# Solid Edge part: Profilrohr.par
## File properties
Username: ahadarics
Dokumentum tartalom típus: 0
Author: ahadarics
Last saved by: ahadarics
Revision: 85
Sűrűség: 0,000 kg/m^3
Pontosság: 0,990
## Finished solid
Body 1: solid body, 6 faces, 6 edges, 0 vertices.
  Faces by surface: cone 2, cylinder 2, plane 2
  Edges by curve: circle 6
Bounding box of the edges (mm): 13.270 x 13.270 x 347.000, from (-6.635, -6.635, -328.5) to (6.635, 6.635, 18.5).
Cylindrical faces by radius (mm): R6 x1, R6.635 x1
Conical faces (half-angle, radius in mm at the cone's reference point): 15 deg R6.067 x2
Planar faces by outward normal: +z 1, -z 1
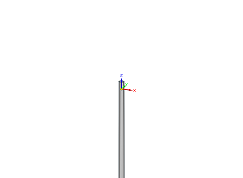
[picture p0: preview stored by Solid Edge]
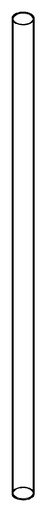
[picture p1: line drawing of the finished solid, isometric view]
